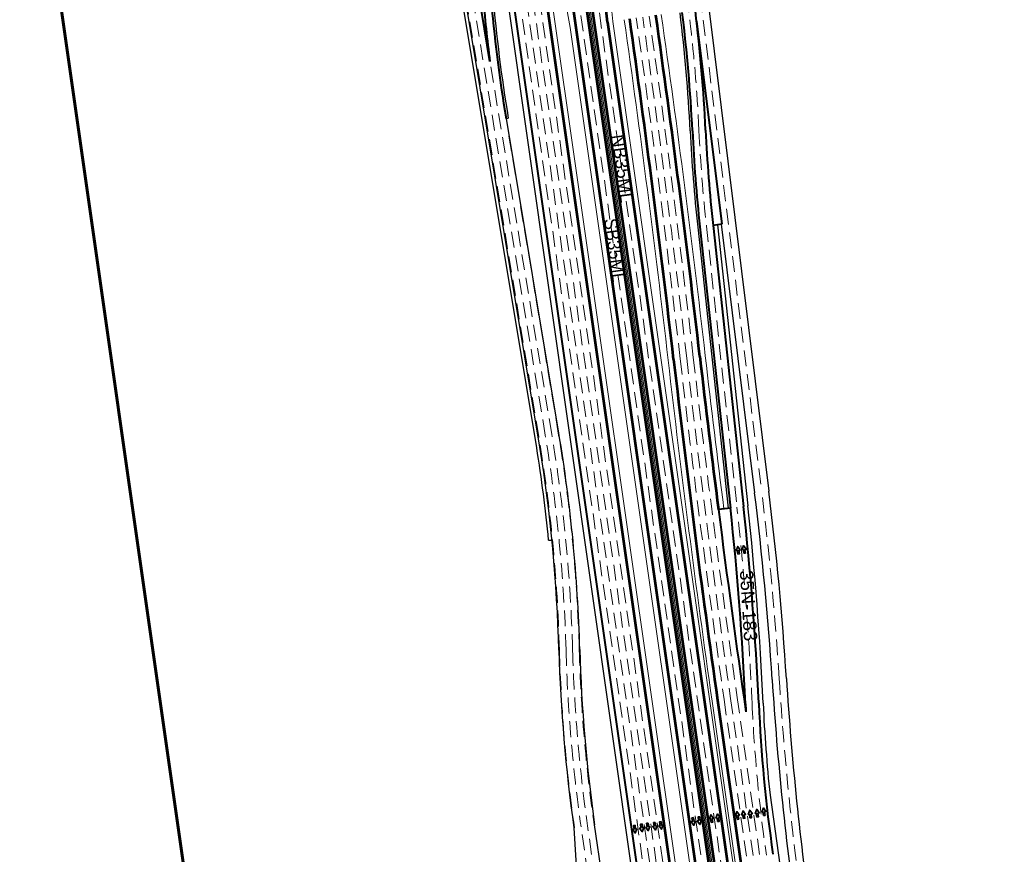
# Model space of a CAD drawing. Extents: x 2329387 to 2347382, y 6951580 to 6987999.
# Drawn here: x 2329937 to 2331724, y 6970749 to 6972265 of the extents above; entities that cross this region are included whole.
import ezdxf

# ---------------------------------------------------------------- set-up
doc = ezdxf.new("R2010")
doc.units = 0
doc.header["$LTSCALE"] = 9.6
doc.linetypes.add('MEDIUM_DASHED', pattern=[4.5, 3, -1.5])
for name, color, linetype, lineweight in [('26', 7, 'Continuous', 53), ('27', 7, 'Continuous', 40), ('28', 7, 'Continuous', 25), ('30', 7, 'Continuous', 13), ('41', 7, 'Continuous', 35), ('50', 7, 'MEDIUM_DASHED', 13), ('62', 7, 'Continuous', 60)]:
    doc.layers.add(name, color=color, linetype=linetype, lineweight=lineweight)
doc.layers.add('40', color=7, linetype='Continuous')

msp = doc.modelspace()

# ---------------------------------------------------------------- linework, layer by layer
at = {"layer": '26'}
for p, q in [((2330667.024, 6973887.048), (2331238.034, 6969888.911)), ((2331204.547, 6971028.714), (2331531.518, 6968739.307))]:
    msp.add_line(p, q, dxfattribs=at)
at = {"layer": '26', "lineweight": 13}
for p, q in [((2330676.924, 6973888.462), (2331247.933, 6969890.325)), ((2331194.647, 6971027.301), (2331508.441, 6968830.155))]:
    msp.add_line(p, q, dxfattribs=at)
at = {"layer": '26', "lineweight": 25}
for p, q in [((2330789.899, 6972531.591), (2331064.905, 6970606.033)), ((2331299.907, 6970856.121), (2331540.622, 6969170.663))]:
    msp.add_line(p, q, dxfattribs=at)
at = {"layer": '26', "lineweight": 40}
msp.add_line((2330804.221, 6972502.04), (2331070.987, 6970634.178), dxfattribs=at)
at = {"layer": '26', "lineweight": 13}
for centre, radius, start, end in [((2308356.799, 6969026.552), 22908.312, 6.56743, 8.12796), ((2308356.799, 6969026.552), 22976.312, 6.56743, 8.12795), ((2353892.64, 6974269.002), 22928.312, 186.56743, 188.12795), ((2353892.64, 6974269.002), 22860.312, 186.56743, 187.26904)]:
    msp.add_arc(centre, radius, start, end, dxfattribs=at)
at = {"layer": '26'}
for centre, radius, start, end in [((2308356.799, 6969026.552), 22918.312, 6.56743, 8.12793), ((2308356.799, 6969026.552), 22966.312, 6.56743, 8.12795), ((2353892.64, 6974269.002), 22918.312, 186.56743, 188.12795), ((2353892.64, 6974269.002), 22870.312, 186.56743, 187.26904)]:
    msp.add_arc(centre, radius, start, end, dxfattribs=at)
at = {"layer": '27'}
for p, q in [((2330790.973, 6972189.308), (2330734.176, 6972531.404)), ((2331166.575, 6972262.46), (2331212.31, 6971893.837)), ((2331196.308, 6971891.731), (2331251.768, 6971381.075)), ((2331212.31, 6971893.837), (2331196.312, 6971891.732)), ((2331172.448, 6971889.14), (2331227.956, 6971378.038)), ((2331227.956, 6971378.038), (2331206.137, 6971375.255))]:
    msp.add_line(p, q, dxfattribs=at)
at = {"layer": '27', "lineweight": 25}
for p, q in [((2330820.34, 6972085.69), (2330824.286, 6972086.345)), ((2331204.261, 6971892.595), (2331259.721, 6971381.939)), ((2331168.471, 6971888.717), (2331223.98, 6971377.606))]:
    msp.add_line(p, q, dxfattribs=at)
at = {"layer": '27'}
for centre, radius, start, end in [((2333632.632, 6972552.607), 2864.789, 184.88383, 187.28559), ((2333632.632, 6972552.607), 2850.789, 184.88383, 189.42666), ((2328321.259, 6971928.47), 2840.789, 2.72676, 7.07261), ((2328321.259, 6971928.47), 2864.789, 2.72676, 7.07261), ((2334044.35, 6972201.043), 2888.789, 182.72676, 186.19832), ((2334044.35, 6972201.043), 2864.789, 182.72676, 186.19832), ((2353892.64, 6974269.002), 22870.312, 187.26904, 188.1981), ((2325555.684, 6970762.451), 5705.578, 2.61081, 6.19832), ((2325555.684, 6970762.451), 5729.578, 2.61081, 6.19832), ((2334141.13, 6971153.937), 2888.789, 182.61081, 182.90001), ((2334141.13, 6971153.937), 2864.789, 182.61081, 188.12795)]:
    msp.add_arc(centre, radius, start, end, dxfattribs=at)
at = {"layer": '27', "lineweight": 25}
for centre, radius, start, end in [((2333632.632, 6972552.607), 2846.789, 184.88383, 189.42666), ((2328321.259, 6971928.47), 2836.789, 2.72676, 7.07261), ((2334044.35, 6972201.043), 2892.789, 182.72676, 186.19815), ((2325555.684, 6970762.451), 5737.578, 2.61081, 6.19832), ((2334141.13, 6971153.937), 2856.789, 182.61081, 185.98388)]:
    msp.add_arc(centre, radius, start, end, dxfattribs=at)
at = {"layer": '28'}
for p, q in [((2330881.902, 6971488.571), (2330490.933, 6973843.423)), ((2331005.133, 6973766.707), (2331297.68, 6971408.806)), ((2330875.983, 6971487.588), (2330590.714, 6973205.798)), ((2330916.201, 6971514.417), (2330821.327, 6972085.854)), ((2331211.318, 6971893.714), (2331271.878, 6971405.605)), ((2330897.61, 6971319.422), (2330903.581, 6971320.011)), ((2331044.015, 6970361.02), (2330981.271, 6970802.348)), ((2330943.65, 6970796.999), (2330952.882, 6970646.803))]:
    msp.add_line(p, q, dxfattribs=at)
for centre, radius, start, end in [((2328053.6, 6971039.135), 2901.789, 1.61259, 9.4269), ((2328053.6, 6971039.135), 2857.789, 5.62852, 9.02919), ((2328053.6, 6971039.135), 2863.789, 1.61259, 9.02919), ((2325610.707, 6970703.217), 5730.578, 3.65453, 7.07261), ((2325610.707, 6970703.217), 5704.578, 3.65453, 7.07261), ((2333780.908, 6971200.373), 2865.789, 181.61259, 188.09153), ((2333780.908, 6971200.373), 2827.789, 181.61259, 188.09153), ((2337046.561, 6971433.627), 5728.578, 183.65453, 188.12795), ((2337046.561, 6971433.627), 5754.578, 183.65453, 188.12795)]:
    msp.add_arc(centre, radius, start, end, dxfattribs=at)
at = {"layer": '30', "lineweight": 53}
for p, q in [((2330735.905, 6973899.861), (2331296.241, 6969976.458)), ((2330745.804, 6973901.275), (2331470.823, 6968824.782)), ((2331004.304, 6972261.043), (2330973.768, 6972559.727)), ((2330929.213, 6972376.588), (2331192.676, 6970531.853)), ((2331004.304, 6972261.043), (2331494.582, 6968828.175))]:
    msp.add_line(p, q, dxfattribs=at)
at = {"layer": '30'}
for p, q in [((2330739.864, 6973900.426), (2331300.2, 6969977.023)), ((2330741.844, 6973900.709), (2331466.866, 6968824.195)), ((2330860.069, 6972669.757), (2330936.987, 6972251.429)), ((2331014.231, 6972262.259), (2330983.696, 6972560.942)), ((2330936.987, 6972251.429), (2331182.776, 6970530.44)), ((2331014.231, 6972262.259), (2331504.482, 6968829.589))]:
    msp.add_line(p, q, dxfattribs=at)
at = {"layer": '41'}
for points in [[(2331241.379, 6971294.261), (2331244.352, 6971294.672), (2331243.419, 6971301.415), (2331245.833, 6971301.749), (2331241.103, 6971308.363), (2331238.347, 6971300.713), (2331240.446, 6971301.004)], [(2331252.253, 6971295.863), (2331255.226, 6971296.275), (2331254.293, 6971303.017), (2331256.707, 6971303.351), (2331251.977, 6971309.965), (2331249.221, 6971302.315), (2331251.32, 6971302.606)], [(2331192.921, 6970806.68), (2331195.893, 6970807.092), (2331194.957, 6970813.834), (2331197.371, 6970814.17), (2331192.637, 6970820.781), (2331189.885, 6970813.13), (2331191.985, 6970813.421)], [(2331204.711, 6970808.35), (2331207.683, 6970808.763), (2331206.747, 6970815.505), (2331209.161, 6970815.841), (2331204.427, 6970822.452), (2331201.675, 6970814.801), (2331203.774, 6970815.092)], [(2331239.954, 6970812.473), (2331242.927, 6970812.884), (2331241.993, 6970819.627), (2331244.408, 6970819.961), (2331239.678, 6970826.575), (2331236.922, 6970818.925), (2331239.021, 6970819.216)], [(2331251.144, 6970813.97), (2331254.117, 6970814.381), (2331253.184, 6970821.123), (2331255.598, 6970821.458), (2331250.868, 6970828.072), (2331248.112, 6970820.422), (2331250.211, 6970820.712)], [(2331263.298, 6970815.054), (2331266.27, 6970815.466), (2331265.337, 6970822.208), (2331267.752, 6970822.542), (2331263.021, 6970829.157), (2331260.265, 6970821.506), (2331262.365, 6970821.797)], [(2331275.936, 6970816.577), (2331278.908, 6970816.988), (2331277.975, 6970823.73), (2331280.389, 6970824.065), (2331275.659, 6970830.679), (2331272.903, 6970823.029), (2331275.003, 6970823.319)], [(2331288.036, 6970819.264), (2331291.008, 6970819.676), (2331290.075, 6970826.418), (2331292.49, 6970826.752), (2331287.759, 6970833.366), (2331285.003, 6970825.716), (2331287.103, 6970826.007)], [(2331054.786, 6970801.605), (2331051.814, 6970801.192), (2331052.75, 6970794.451), (2331050.336, 6970794.115), (2331055.07, 6970787.503), (2331057.822, 6970795.155), (2331055.722, 6970794.863)], [(2331067.337, 6970804.111), (2331064.364, 6970803.698), (2331065.301, 6970796.956), (2331062.887, 6970796.621), (2331067.62, 6970790.009), (2331070.373, 6970797.661), (2331068.273, 6970797.369)], [(2331078.459, 6970805.731), (2331075.487, 6970805.318), (2331076.424, 6970798.576), (2331074.01, 6970798.241), (2331078.743, 6970791.629), (2331081.495, 6970799.28), (2331079.396, 6970798.989)], [(2331091.222, 6970806.973), (2331088.249, 6970806.56), (2331089.186, 6970799.818), (2331086.772, 6970799.483), (2331091.505, 6970792.871), (2331094.257, 6970800.522), (2331092.158, 6970800.231)], [(2331102.344, 6970808.593), (2331099.372, 6970808.18), (2331100.309, 6970801.438), (2331097.895, 6970801.102), (2331102.628, 6970794.491), (2331105.38, 6970802.142), (2331103.281, 6970801.851)], [(2331160.953, 6970815.561), (2331157.981, 6970815.148), (2331158.917, 6970808.406), (2331156.503, 6970808.07), (2331161.237, 6970801.459), (2331163.989, 6970809.11), (2331161.889, 6970808.819)], [(2331172.076, 6970817.18), (2331169.103, 6970816.768), (2331170.04, 6970810.026), (2331167.626, 6970809.69), (2331172.36, 6970803.078), (2331175.112, 6970810.73), (2331173.012, 6970810.438)]]:
    msp.add_lwpolyline(points, close=True, dxfattribs=at)
at = {"layer": '50'}
for p, q in [((2330724.025, 6973898.164), (2331204.555, 6970533.55)), ((2330757.684, 6973902.971), (2331482.703, 6968826.479)), ((2330631.386, 6973881.958), (2331606.386, 6967055.128)), ((2330643.265, 6973883.655), (2331618.272, 6967056.781)), ((2330655.145, 6973885.352), (2331630.147, 6967058.504)), ((2330879.702, 6971508.348), (2330491.987, 6973843.598)), ((2330891.543, 6971510.297), (2330503.823, 6973845.574)), ((2330992.232, 6973765.107), (2331284.779, 6971407.206)), ((2330770.63, 6972822.111), (2331098.035, 6970529.663)), ((2330903.377, 6971512.286), (2330790.973, 6972189.308)), ((2330915.218, 6971514.231), (2330820.34, 6972085.69)), ((2331184.377, 6971890.445), (2331239.838, 6971379.779)), ((2331228.306, 6971032.108), (2331555.277, 6968742.7)), ((2331240.185, 6971033.804), (2331567.156, 6968744.397)), ((2331216.426, 6971030.411), (2331543.397, 6968741.003)), ((2331139.96, 6969593.801), (2330968.401, 6970800.518)), ((2331637.49, 6966009.015), (2330956.52, 6970798.829))]:
    msp.add_line(p, q, dxfattribs=at)
for centre, radius, start, end in [((2308356.799, 6969026.552), 22930.312, 6.56743, 8.12795), ((2308356.799, 6969026.552), 22942.312, 6.56743, 8.12795), ((2308356.799, 6969026.552), 22954.312, 6.56743, 8.12799), ((2328321.259, 6971928.47), 2852.789, 2.72676, 7.07261), ((2334044.35, 6972201.043), 2876.789, 182.72676, 186.19813), ((2353892.64, 6974269.002), 22906.312, 186.56743, 188.12795), ((2353892.64, 6974269.002), 22894.312, 186.56743, 188.12795), ((2353892.64, 6974269.002), 22882.312, 186.56743, 188.12795), ((2328053.6, 6971039.135), 2864.789, 1.61259, 9.42673), ((2328053.6, 6971039.135), 2876.789, 1.61259, 9.4264), ((2328053.6, 6971039.135), 2888.789, 1.61259, 9.42688), ((2328053.6, 6971039.135), 2900.789, 1.61259, 9.42646), ((2325610.707, 6970703.217), 5717.578, 3.65453, 7.07261), ((2325555.684, 6970762.451), 5717.578, 2.61081, 6.19832), ((2333780.908, 6971200.373), 2864.789, 181.61259, 188.09153), ((2333780.908, 6971200.373), 2852.789, 181.61259, 188.09153), ((2333780.908, 6971200.373), 2840.789, 181.61259, 188.09153), ((2333780.908, 6971200.373), 2828.789, 181.61259, 188.09153), ((2337046.561, 6971433.627), 5741.578, 183.65453, 188.12795), ((2334141.13, 6971153.937), 2876.789, 182.61081, 188.12795)]:
    msp.add_arc(centre, radius, start, end, dxfattribs=at)
at = {"layer": '62'}
msp.add_lwpolyline([(2329936.564, 6972812.843), (2331011.084, 6965289.186), (2332891.999, 6965557.816), (2331817.479, 6973081.473)], close=True, dxfattribs=at)

# ---------------------------------------------------------------- texts
at = {"layer": '40'}
msp.add_text('NB35ML', height=24, rotation=277.885, dxfattribs=at).set_placement((2331011.51, 6972055.156))
for s, rotation, width, p in [('SB35ML', 277.885, 0.95, (2330998.102, 6971902.675)), ('35N-183', 273.534, 1.05, (2331245.068, 6971264.531))]:
    msp.add_text(s, height=24, rotation=rotation, dxfattribs=dict(at, width=width)).set_placement(p)

doc.saveas('drawing.dxf')
